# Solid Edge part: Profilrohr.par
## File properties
Username: bmolnar
Dokumentum tartalom típus: 0
Author: bmolnar
Last saved by: bmolnar
Revision: 83
Sűrűség: 0,000 kg/m^3
Pontosság: 0,990
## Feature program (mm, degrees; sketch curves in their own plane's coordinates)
base feature "unnamed BaseFeature 1"
thread "unnamed Thread 1"
thread "Menet_2"  ThreadDepth = 9.3 mm
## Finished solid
Body 1: solid body, 157 faces, 384 edges, 249 vertices.
  Faces by surface: plane 79, cylinder 66, cone 8, torus 4
  Edges by curve: line 236, circle 140, curve on surface 8
Bounding box of the edges (mm; curved faces can reach further): 100.000 x 105.000 x 106.000, from (-50, -50, 0) to (50, 55, 106).
Cylindrical faces by radius (mm): R0.2 x24, R2.15 x2, R4.5 x4, R5.5 x4, R5.7225 x4, R7 x8, R8.5 x8, R40 x1, R40.1 x1, R40.85 x2, R41.05 x2, R42.8 x2, R67.3474 x1, R67.5 x3
Conical faces (half-angle, radius in mm at the cone's reference point): 30 deg R40.325 x2, 30 deg R41.1387 x2, 45 deg R6.0725 x2, 45 deg R41.15 x2
Toroidal faces (ring radius, tube radius in mm): R42.6 r0.2 x4
Planar faces by outward normal: +x 9, +y 11, +z 9, -x 9, -y 9, -z 8, oblique 24
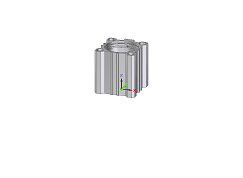
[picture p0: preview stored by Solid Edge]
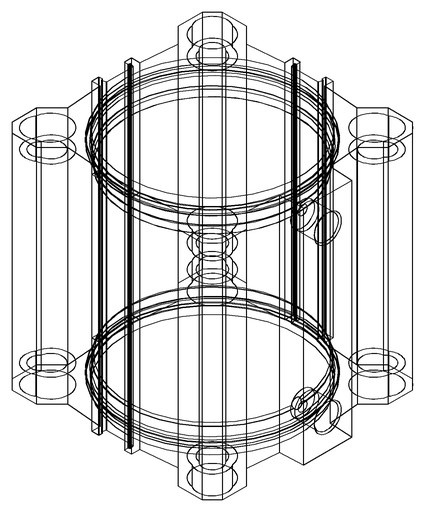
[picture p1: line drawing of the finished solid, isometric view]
